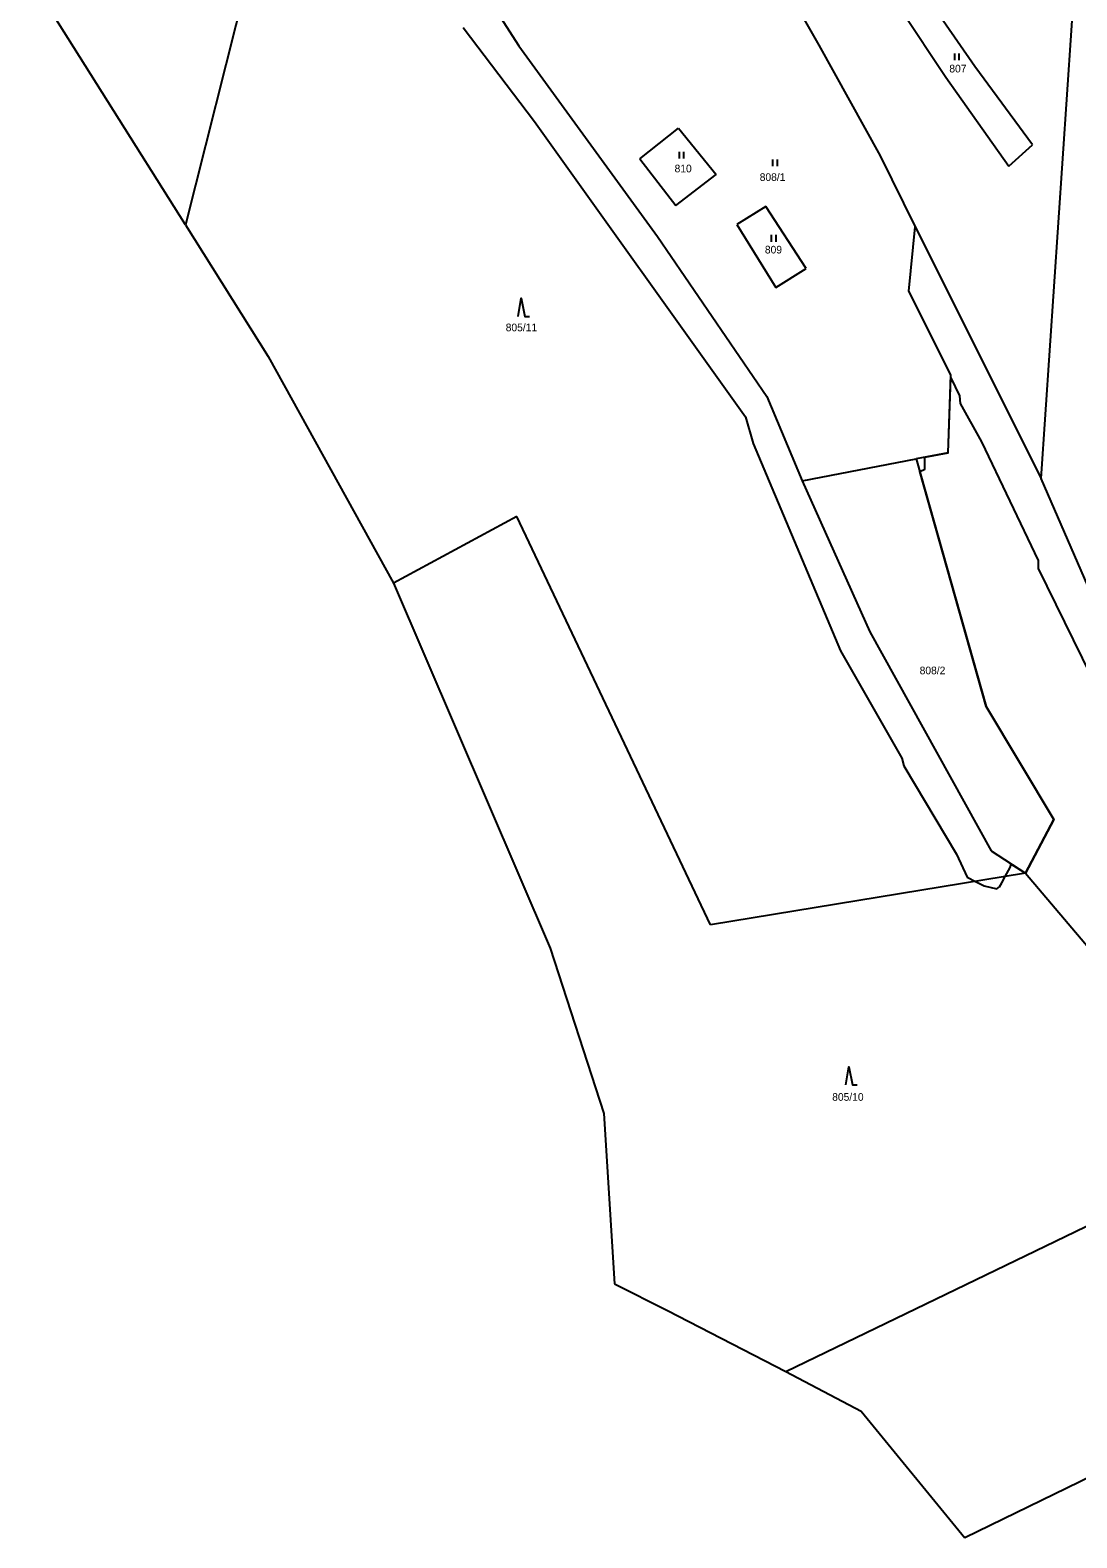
# Model space of a CAD drawing. Extents: x -439246 to -433691, y -1130252 to -1121148.
# Drawn here: x -437792.2 to -437560.4, y -1125023.3 to -1124689.3 of the extents above; entities that cross this region are included whole.
import ezdxf

# ---------------------------------------------------------------- set-up
doc = ezdxf.new("R2010")
doc.units = 0
for name, color, linetype in [('Vrstva 1', 7, 'Continuous'), ('Vrstva 18', 7, 'Continuous'), ('Vrstva 25', 7, 'Continuous'), ('Vrstva 52', 7, 'Continuous'), ('Vrstva 6', 7, 'Continuous')]:
    doc.layers.add(name, color=color, linetype=linetype)

msp = doc.modelspace()

# ---------------------------------------------------------------- linework, layer by layer
at = {"layer": 'Vrstva 1'}
for points in [[(-437582.95, -1124697.37), (-437604.02, -1124666.98)], [(-437609.03, -1124670.13), (-437589.4, -1124699.73)], [(-437568.3, -1124788.64), (-437560.61, -1124675.18)], [(-437691.59, -1124680.96), (-437683.98, -1124692.81)], [(-437623.1, -1124682.87), (-437617.55, -1124692.64)], [(-437683.98, -1124692.81), (-437653.24, -1124735.02)], [(-437617.55, -1124692.64), (-437603.95, -1124717.16)], [(-437570.22, -1124714.71), (-437582.95, -1124697.37)], [(-437589.4, -1124699.73), (-437575.48, -1124719.49)], [(-437657.15, -1124717.81), (-437648.6, -1124711.02)], [(-437648.6, -1124711.02), (-437640.25, -1124721.33)], [(-437575.48, -1124719.49), (-437570.22, -1124714.71)], [(-437657.15, -1124717.81), (-437649.22, -1124728.19)], [(-437603.95, -1124717.16), (-437596.21, -1124732.88)], [(-437649.22, -1124728.19), (-437640.25, -1124721.33)], [(-437629.26, -1124728.42), (-437635.69, -1124732.42)], [(-437620.32, -1124742.17), (-437629.26, -1124728.42)], [(-437635.69, -1124732.42), (-437627.04, -1124746.35)], [(-437597.57, -1124747.17), (-437596.21, -1124732.88)], [(-437596.21, -1124732.88), (-437568.3, -1124788.64)], [(-437653.24, -1124735.02), (-437629, -1124770.5)], [(-437627.04, -1124746.35), (-437620.32, -1124742.17)], [(-437588.27, -1124765.71), (-437597.57, -1124747.17)], [(-437588.91, -1124782.96), (-437588.27, -1124765.71)], [(-437629, -1124770.5), (-437621.21, -1124789.2)], [(-437588.91, -1124782.96), (-437595.97, -1124784.32)], [(-437621.21, -1124789.2), (-437595.97, -1124784.32)], [(-437595.97, -1124784.32), (-437580.5, -1124839.14)], [(-437621.21, -1124789.2), (-437606.24, -1124822.61)], [(-437517.61, -1124905.18), (-437568.3, -1124788.64)], [(-437606.24, -1124822.61), (-437579.38, -1124871.11)], [(-437580.5, -1124839.14), (-437565.5, -1124864.17)], [(-437565.5, -1124864.17), (-437571.77, -1124876.1)], [(-437579.38, -1124871.11), (-437571.77, -1124876.1)], [(-437571.77, -1124876.1), (-437520.84, -1124936.19)]]:
    msp.add_lwpolyline(points, dxfattribs=at)
at = {"layer": 'Vrstva 25'}
for p, q in [((-437587.41, -1124696.01), (-437587.41, -1124694.51)), ((-437586.41, -1124696.01), (-437586.41, -1124694.51)), ((-437648.4, -1124717.77), (-437648.4, -1124716.27)), ((-437647.4, -1124717.77), (-437647.4, -1124716.27)), ((-437627.69, -1124719.5), (-437627.69, -1124718)), ((-437626.69, -1124719.5), (-437626.69, -1124718)), ((-437628, -1124736.21), (-437628, -1124734.71)), ((-437627, -1124736.21), (-437627, -1124734.71))]:
    msp.add_line(p, q, dxfattribs=at)
for points in [[(-437684.12, -1124752.74), (-437683.42, -1124748.74), (-437682.62, -1124752.74), (-437681.62, -1124752.74)], [(-437611.54, -1124922.96), (-437610.84, -1124918.96), (-437610.04, -1124922.96), (-437609.04, -1124922.96)]]:
    msp.add_lwpolyline(points, dxfattribs=at)
at = {"layer": 'Vrstva 52'}
for points in [[(-437696.25, -1124688.72), (-437680.52, -1124709.54), (-437633.78, -1124774.98), (-437632.08, -1124780.93), (-437612.75, -1124826.82), (-437599.15, -1124850.62), (-437598.73, -1124852.32), (-437587.04, -1124871.87), (-437584.7, -1124876.97), (-437582.82, -1124877.91), (-437580.88, -1124878.88), (-437578.11, -1124879.52), (-437577.75, -1124879.28), (-437577.48, -1124879.09), (-437576.98, -1124878.19), (-437576.23, -1124876.83), (-437575.14, -1124874.84), (-437574.9, -1124874.05), (-437571.77, -1124876.1), (-437565.5, -1124864.17), (-437580.5, -1124839.14), (-437595.18, -1124787.12), (-437594.05, -1124786.62), (-437594.05, -1124783.95), (-437588.91, -1124782.96), (-437588.29, -1124766.33), (-437586.4, -1124770.31)], [(-437586.4, -1124770.31), (-437586.19, -1124772.01), (-437581.51, -1124780.51), (-437568.98, -1124806.85), (-437568.98, -1124808.55), (-437557.29, -1124832.35)]]:
    msp.add_lwpolyline(points, dxfattribs=at)
at = {"layer": 'Vrstva 6'}
for points in [[(-437757.75, -1124732.5), (-437792.17, -1124677.73)], [(-437744.38, -1124679.36), (-437757.75, -1124732.5)], [(-437757.75, -1124732.5), (-437739.44, -1124761.64)], [(-437739.44, -1124761.64), (-437711.71, -1124811.83)], [(-437684.41, -1124797.06), (-437711.71, -1124811.83)], [(-437641.52, -1124887.5), (-437684.41, -1124797.06)], [(-437711.71, -1124811.83), (-437677.04, -1124892.69)], [(-437571.77, -1124876.1), (-437641.52, -1124887.5)], [(-437677.04, -1124892.69), (-437665.13, -1124929.28)], [(-437665.13, -1124929.28), (-437662.79, -1124967.01)], [(-437624.82, -1124986.46), (-437520.84, -1124936.19)], [(-437662.79, -1124967.01), (-437651.04, -1124972.96)], [(-437651.04, -1124972.96), (-437624.82, -1124986.46)], [(-437497.59, -1124980.59), (-437585.17, -1125023.3)], [(-437624.82, -1124986.46), (-437608.17, -1124995.23)], [(-437608.17, -1124995.23), (-437585.17, -1125023.3)]]:
    msp.add_lwpolyline(points, dxfattribs=at)

# ---------------------------------------------------------------- texts
at = {"layer": 'Vrstva 18'}
for s, p in [('807', (-437588.62, -1124698.71)), ('810', (-437649.46, -1124720.84)), ('808/1', (-437630.61, -1124722.74)), ('809', (-437629.47, -1124738.81)), ('805/11', (-437686.86, -1124756.04)), ('808/2', (-437595.19, -1124832.02)), ('805/10', (-437614.56, -1124926.49))]:
    msp.add_text(s, height=1.7, dxfattribs=at).set_placement(p)

doc.saveas('drawing.dxf')
